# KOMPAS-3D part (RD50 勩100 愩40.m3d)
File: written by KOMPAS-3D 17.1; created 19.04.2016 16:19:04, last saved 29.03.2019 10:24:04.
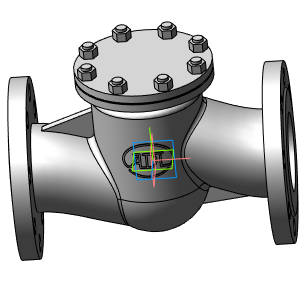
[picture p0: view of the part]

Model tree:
1. Операция без истории:2  (labels: Сталь 20  ГОСТ 1050-88)

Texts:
  RD50 Ду15 Ру40
  RD50 Ду20 Ру40
  RD50 Ду25 Ру40
  RD50 Ду32 Ру40
  RD50 Ду40 Ру40
  RD50 Ду50 Ру40
  RD50 Ду65 Ру40
  RD50 Ду80 Ру40
  RD50 Ду100 Ру40
  RD50 Ду125 Ру40
  RD50 Ду150 Ру40
  RD50 Ду200 Ру40
  RD50 Ду250 Ру40
  RD50 Ду300 Ру40
  RD50 Ду350 Ру40
  RD50 Ду400 Ру40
